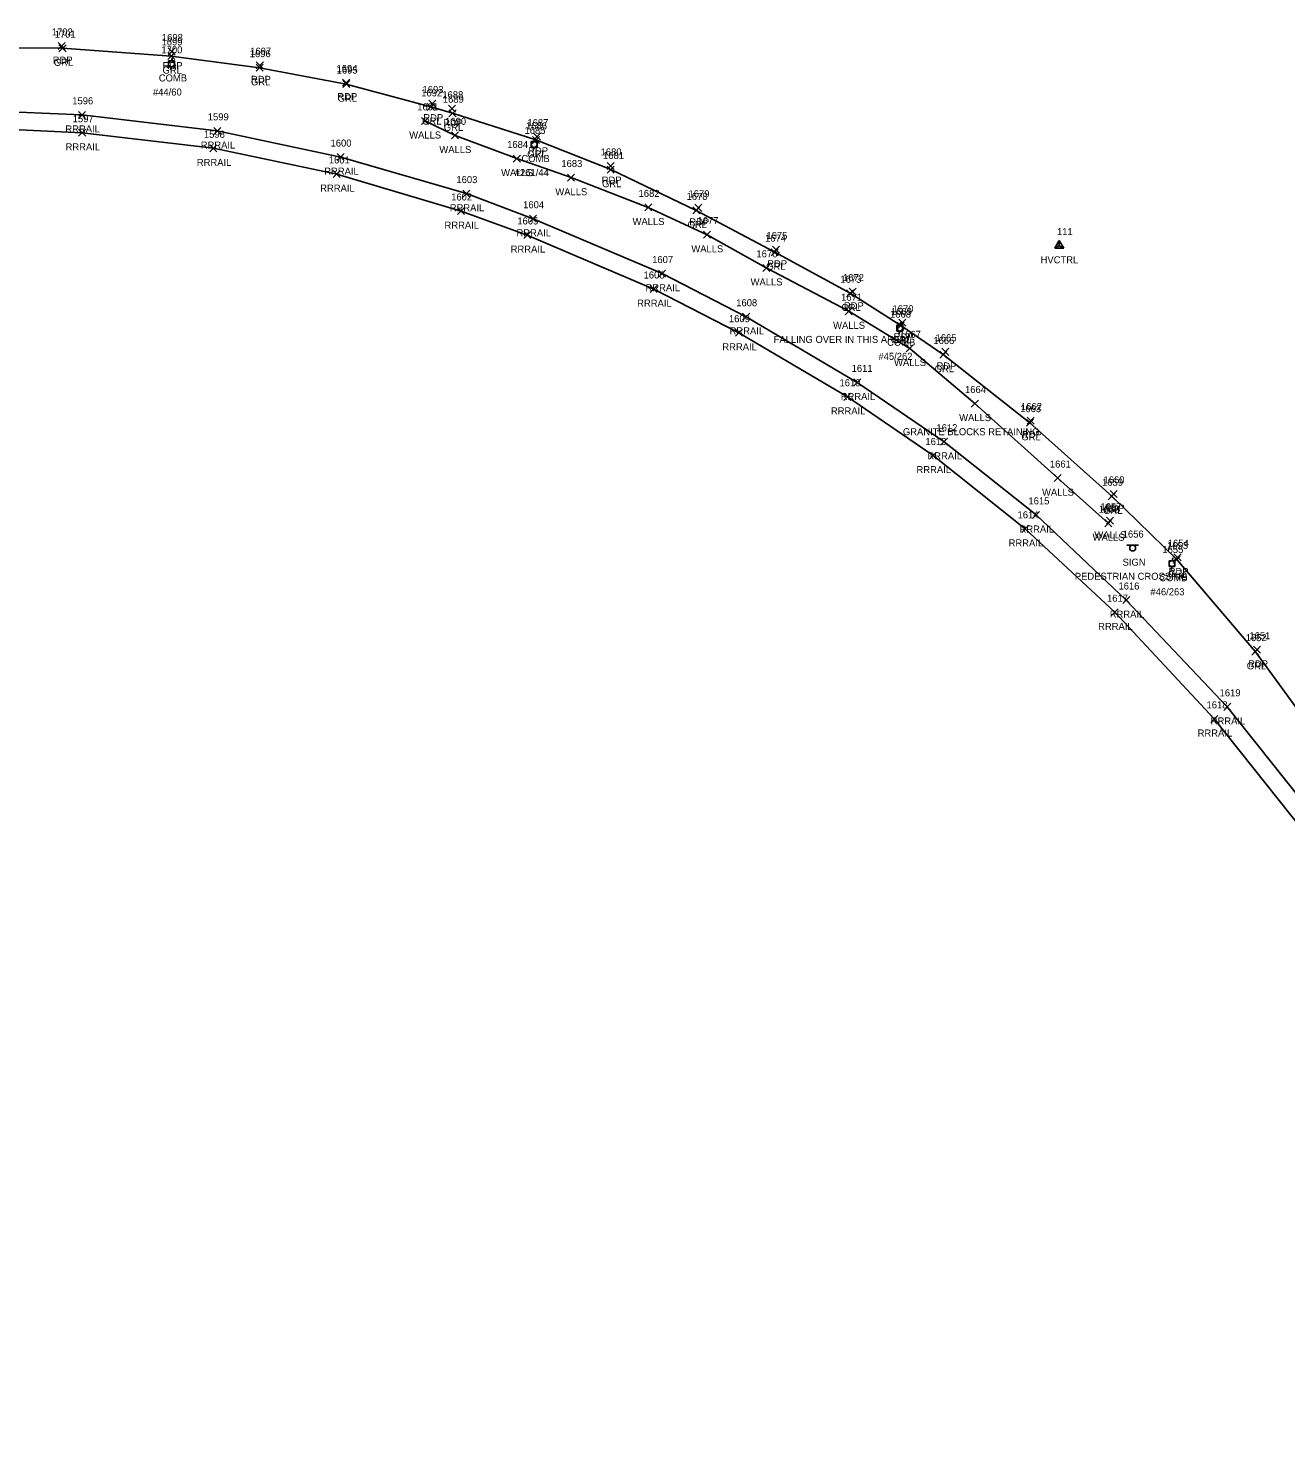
# Model space of a CAD drawing. Extents: x 1635588 to 1637550, y 621583 to 623638.
# Drawn here: x 1635936.7 to 1636293.9, y 623212.1 to 623614.3 of the extents above; entities that cross this region are included whole.
import ezdxf

# ---------------------------------------------------------------- set-up
doc = ezdxf.new("R2010")
doc.units = 0
for name, color, linetype in [('C_A', 7, 'Continuous'), ('C_I', 7, 'Continuous'), ('CPSM', 7, 'Continuous'), ('L_A', 7, 'Continuous'), ('L_C', 7, 'Continuous'), ('L_I', 7, 'Continuous'), ('L_TIC', 7, 'Continuous'), ('LWS', 7, 'Continuous'), ('P_A', 7, 'Continuous'), ('P_I', 7, 'Continuous'), ('P_TIC', 7, 'Continuous'), ('R_A', 7, 'Continuous'), ('R_I', 7, 'Continuous'), ('R_TIC', 7, 'Continuous'), ('RGR', 7, 'Continuous'), ('RR', 7, 'Continuous'), ('S_A', 7, 'Continuous'), ('S_C', 7, 'Continuous'), ('S_I', 7, 'Continuous'), ('SSGN', 7, 'Continuous'), ('U_A', 7, 'Continuous'), ('U_C', 7, 'Continuous'), ('U_I', 7, 'Continuous'), ('UP', 7, 'Continuous')]:
    doc.layers.add(name, color=color, linetype=linetype)

msp = doc.modelspace()

# ---------------------------------------------------------------- linework, layer by layer
at = {"layer": 'CPSM'}
for p, q in [((1636228.33, 623551.79), (1636229.58, 623553.95)), ((1636230.83, 623551.79), (1636229.58, 623553.95)), ((1636229.58, 623552.51), (1636229.58, 623553.95)), ((1636228.33, 623551.79), (1636229.58, 623552.51)), ((1636228.33, 623551.79), (1636230.83, 623551.79)), ((1636229.58, 623552.51), (1636229.58, 623552.51)), ((1636229.58, 623552.51), (1636230.83, 623551.79))]:
    msp.add_line(p, q, dxfattribs=at)
at = {"layer": 'L_TIC'}
for points in [[(1636048.39, 623586.97), (1636050.39, 623588.97)], [(1636050.39, 623586.97), (1636048.39, 623588.97)], [(1636056.96, 623582.85), (1636058.96, 623584.85)], [(1636058.96, 623582.85), (1636056.96, 623584.85)], [(1636074.5, 623576.28), (1636076.5, 623578.28)], [(1636076.5, 623576.28), (1636074.5, 623578.28)], [(1636089.89, 623570.85), (1636091.89, 623572.85)], [(1636091.89, 623570.85), (1636089.89, 623572.85)], [(1636111.82, 623562.38), (1636113.82, 623564.38)], [(1636113.82, 623562.38), (1636111.82, 623564.38)], [(1636128.53, 623554.64), (1636130.53, 623556.64)], [(1636130.53, 623554.64), (1636128.53, 623556.64)], [(1636145.36, 623545.21), (1636147.36, 623547.21)], [(1636147.36, 623545.21), (1636145.36, 623547.21)], [(1636168.79, 623532.89), (1636170.79, 623534.89)], [(1636170.79, 623532.89), (1636168.79, 623534.89)], [(1636186.1, 623522.33), (1636188.1, 623524.33)], [(1636188.1, 623522.33), (1636186.1, 623524.33)], [(1636204.59, 623506.66), (1636206.59, 623508.66)], [(1636206.59, 623506.66), (1636204.59, 623508.66)], [(1636228.13, 623485.47), (1636230.13, 623487.47)], [(1636230.13, 623485.47), (1636228.13, 623487.47)], [(1636242.5, 623472.67), (1636244.5, 623474.67)], [(1636244.5, 623472.67), (1636242.5, 623474.67)], [(1636242.99, 623473.35), (1636244.99, 623475.35)], [(1636244.99, 623473.35), (1636242.99, 623475.35)]]:
    msp.add_lwpolyline(points, dxfattribs=at)
at = {"layer": 'LWS'}
msp.add_lwpolyline([(1636243.99, 623474.35), (1636243.5, 623473.67), (1636229.13, 623486.47), (1636205.59, 623507.66), (1636187.1, 623523.33), (1636169.79, 623533.89), (1636146.36, 623546.21), (1636129.53, 623555.64), (1636112.82, 623563.38), (1636090.89, 623571.85), (1636075.5, 623577.28), (1636057.96, 623583.85), (1636049.39, 623587.97)], dxfattribs=at)
at = {"layer": 'P_TIC'}
for points in [[(1635945.19, 623608.25), (1635947.19, 623610.25)], [(1635947.19, 623608.25), (1635945.19, 623610.25)], [(1635976.43, 623606.69), (1635978.43, 623608.69)], [(1635978.43, 623606.69), (1635976.43, 623608.69)], [(1636001.51, 623602.78), (1636003.51, 623604.78)], [(1636003.51, 623602.78), (1636001.51, 623604.78)], [(1636026.03, 623597.88), (1636028.03, 623599.88)], [(1636028.03, 623597.88), (1636026.03, 623599.88)], [(1636050.46, 623591.89), (1636052.46, 623593.89)], [(1636052.46, 623591.89), (1636050.46, 623593.89)], [(1636056.08, 623590.41), (1636058.08, 623592.41)], [(1636058.08, 623590.41), (1636056.08, 623592.41)], [(1636080.24, 623582.48), (1636082.24, 623584.48)], [(1636082.24, 623582.48), (1636080.24, 623584.48)], [(1636101.12, 623574.17), (1636103.12, 623576.17)], [(1636103.12, 623574.17), (1636101.12, 623576.17)], [(1636126.02, 623562.27), (1636128.02, 623564.27)], [(1636128.02, 623562.27), (1636126.02, 623564.27)], [(1636148.13, 623550.4), (1636150.13, 623552.4)], [(1636150.13, 623550.4), (1636148.13, 623552.4)], [(1636169.89, 623538.45), (1636171.89, 623540.45)], [(1636171.89, 623538.45), (1636169.89, 623540.45)], [(1636184.03, 623529.61), (1636186.03, 623531.61)], [(1636186.03, 623529.61), (1636184.03, 623531.61)], [(1636196.22, 623521.36), (1636198.22, 623523.36)], [(1636198.22, 623521.36), (1636196.22, 623523.36)], [(1636220.48, 623501.83), (1636222.48, 623503.83)], [(1636222.48, 623501.83), (1636220.48, 623503.83)], [(1636244.02, 623480.98), (1636246.02, 623482.98)], [(1636246.02, 623480.98), (1636244.02, 623482.98)], [(1636262.15, 623462.97), (1636264.15, 623464.97)], [(1636264.15, 623462.97), (1636262.15, 623464.97)], [(1636284.73, 623436.69), (1636286.73, 623438.69)], [(1636286.73, 623436.69), (1636284.73, 623438.69)]]:
    msp.add_lwpolyline(points, dxfattribs=at)
at = {"layer": 'R_TIC'}
for points in [[(1635945.46, 623607.63), (1635947.46, 623609.63)], [(1635947.46, 623607.63), (1635945.46, 623609.63)], [(1635976.33, 623605.41), (1635978.33, 623607.41)], [(1635978.33, 623605.41), (1635976.33, 623607.41)], [(1636001.44, 623602.08), (1636003.44, 623604.08)], [(1636003.44, 623602.08), (1636001.44, 623604.08)], [(1636026.07, 623597.42), (1636028.07, 623599.42)], [(1636028.07, 623597.42), (1636026.07, 623599.42)], [(1635950.97, 623588.69), (1635952.97, 623590.69)], [(1635952.97, 623588.69), (1635950.97, 623590.69)], [(1636050.08, 623590.93), (1636052.08, 623592.93)], [(1636052.08, 623590.93), (1636050.08, 623592.93)], [(1636056.23, 623589.14), (1636058.23, 623591.14)], [(1636058.23, 623589.14), (1636056.23, 623591.14)], [(1635951.04, 623583.59), (1635953.04, 623585.59)], [(1635953.04, 623583.59), (1635951.04, 623585.59)], [(1635989.42, 623584.12), (1635991.42, 623586.12)], [(1635991.42, 623584.12), (1635989.42, 623586.12)], [(1635988.32, 623579.18), (1635990.32, 623581.18)], [(1635990.32, 623579.18), (1635988.32, 623581.18)], [(1636079.92, 623581.58), (1636081.92, 623583.58)], [(1636081.92, 623581.58), (1636079.92, 623583.58)], [(1636024.5, 623576.68), (1636026.5, 623578.68)], [(1636026.5, 623576.68), (1636024.5, 623578.68)], [(1636023.35, 623571.88), (1636025.35, 623573.88)], [(1636025.35, 623571.88), (1636023.35, 623573.88)], [(1636101.16, 623573.13), (1636103.16, 623575.13)], [(1636103.16, 623573.13), (1636101.16, 623575.13)], [(1636060.16, 623566.3), (1636062.16, 623568.3)], [(1636062.16, 623566.3), (1636060.16, 623568.3)], [(1636058.67, 623561.36), (1636060.67, 623563.36)], [(1636060.67, 623561.36), (1636058.67, 623563.36)], [(1636079.11, 623559.16), (1636081.11, 623561.16)], [(1636081.11, 623559.16), (1636079.11, 623561.16)], [(1636125.46, 623561.53), (1636127.46, 623563.53)], [(1636127.46, 623561.53), (1636125.46, 623563.53)], [(1636077.46, 623554.55), (1636079.46, 623556.55)], [(1636079.46, 623554.55), (1636077.46, 623556.55)], [(1636147.75, 623549.67), (1636149.75, 623551.67)], [(1636149.75, 623549.67), (1636147.75, 623551.67)], [(1636115.76, 623543.58), (1636117.76, 623545.58)], [(1636117.76, 623543.58), (1636115.76, 623545.58)], [(1636113.37, 623539.19), (1636115.37, 623541.19)], [(1636115.37, 623539.19), (1636113.37, 623541.19)], [(1636169.14, 623537.98), (1636171.14, 623539.98)], [(1636171.14, 623537.98), (1636169.14, 623539.98)], [(1636139.64, 623531.31), (1636141.64, 623533.31)], [(1636141.64, 623531.31), (1636139.64, 623533.31)], [(1636183.56, 623528.81), (1636185.56, 623530.81)], [(1636185.56, 623528.81), (1636183.56, 623530.81)], [(1636137.58, 623526.78), (1636139.58, 623528.78)], [(1636139.58, 623526.78), (1636137.58, 623528.78)], [(1636195.64, 623520.56), (1636197.64, 623522.56)], [(1636197.64, 623520.56), (1636195.64, 623522.56)], [(1636171.21, 623512.66), (1636173.21, 623514.66)], [(1636173.21, 623512.66), (1636171.21, 623514.66)], [(1636168.41, 623508.57), (1636170.41, 623510.57)], [(1636170.41, 623508.57), (1636168.41, 623510.57)], [(1636220.25, 623501.22), (1636222.25, 623503.22)], [(1636222.25, 623501.22), (1636220.25, 623503.22)], [(1636195.85, 623495.79), (1636197.85, 623497.79)], [(1636197.85, 623495.79), (1636195.85, 623497.79)], [(1636192.73, 623491.88), (1636194.73, 623493.88)], [(1636194.73, 623491.88), (1636192.73, 623493.88)], [(1636243.49, 623480.3), (1636245.49, 623482.3)], [(1636245.49, 623480.3), (1636243.49, 623482.3)], [(1636222, 623475.01), (1636224, 623477.01)], [(1636224, 623475.01), (1636222, 623477.01)], [(1636218.9, 623471.06), (1636220.9, 623473.06)], [(1636220.9, 623471.06), (1636218.9, 623473.06)], [(1636261.93, 623462.31), (1636263.93, 623464.31)], [(1636263.93, 623462.31), (1636261.93, 623464.31)], [(1636247.62, 623450.82), (1636249.62, 623452.82)], [(1636249.62, 623450.82), (1636247.62, 623452.82)], [(1636244.31, 623447.34), (1636246.31, 623449.34)], [(1636246.31, 623447.34), (1636244.31, 623449.34)], [(1636284.27, 623436.15), (1636286.27, 623438.15)], [(1636286.27, 623436.15), (1636284.27, 623438.15)], [(1636276.3, 623420.48), (1636278.3, 623422.48)], [(1636278.3, 623420.48), (1636276.3, 623422.48)], [(1636272.58, 623417.05), (1636274.58, 623419.05)], [(1636274.58, 623417.05), (1636272.58, 623419.05)]]:
    msp.add_lwpolyline(points, dxfattribs=at)
at = {"layer": 'RGR'}
msp.add_lwpolyline([(1636305.19, 623409.8), (1636285.27, 623437.15), (1636262.93, 623463.31), (1636244.49, 623481.3), (1636221.25, 623502.22), (1636196.64, 623521.56), (1636184.56, 623529.81), (1636170.14, 623538.98), (1636148.75, 623550.67), (1636126.46, 623562.53), (1636102.16, 623574.13), (1636080.92, 623582.58), (1636057.23, 623590.14), (1636051.08, 623591.93), (1636027.07, 623598.42), (1636002.44, 623603.08), (1635977.33, 623606.41), (1635946.46, 623608.63), (1635912.43, 623608.87), (1635865.23, 623607.69), (1635827.72, 623606.97)], dxfattribs=at)
at = {"layer": 'RR'}
for points in [[(1635804.38, 623587.78), (1635886, 623591.18), (1635924.86, 623590.87), (1635951.97, 623589.69), (1635990.42, 623585.12), (1636025.5, 623577.68), (1636061.16, 623567.3), (1636080.11, 623560.16), (1636116.76, 623544.58), (1636140.64, 623532.31), (1636172.21, 623513.66), (1636196.85, 623496.79), (1636223, 623476.01), (1636248.62, 623451.82), (1636277.3, 623421.48), (1636310.55, 623379.63), (1636333.74, 623345.07), (1636353.23, 623312.06), (1636372.67, 623275.5), (1636403.41, 623214.43)], [(1635804.54, 623582.78), (1635886.42, 623586.09), (1635924.26, 623585.89), (1635952.04, 623584.59), (1635989.32, 623580.18), (1636024.35, 623572.88), (1636059.67, 623562.36), (1636078.46, 623555.55), (1636114.37, 623540.19), (1636138.58, 623527.78), (1636169.41, 623509.57), (1636193.73, 623492.88), (1636219.9, 623472.06), (1636245.31, 623448.34), (1636273.58, 623418.05), (1636306.45, 623376.76), (1636329.74, 623342.31), (1636348.93, 623309.65), (1636368.15, 623273.24), (1636399.35, 623212.11)]]:
    msp.add_lwpolyline(points, dxfattribs=at)
at = {"layer": 'SSGN'}
for p, q in [((1636248.76, 623467.43), (1636252.09, 623467.43)), ((1636250.41, 623466.6), (1636250.41, 623466.6))]:
    msp.add_line(p, q, dxfattribs=at)
msp.add_circle((1636250.41, 623466.6), 0.833, dxfattribs=at)
at = {"layer": 'UP'}
for p, q in [((1635977.67, 623605.85), (1635977.42, 623605.01)), ((1635976.59, 623603.35), (1635976.59, 623605.01)), ((1635976.59, 623605.01), (1635978.26, 623605.01)), ((1635978.26, 623603.35), (1635976.59, 623603.35)), ((1635977.17, 623602.51), (1635977.42, 623603.35)), ((1635977.42, 623604.18), (1635977.42, 623604.18)), ((1635978.26, 623605.01), (1635978.26, 623603.35)), ((1636079.59, 623580.45), (1636079.59, 623582.12)), ((1636079.59, 623582.12), (1636081.26, 623582.12)), ((1636080.67, 623582.95), (1636080.42, 623582.12)), ((1636080.42, 623581.28), (1636080.42, 623581.28)), ((1636081.26, 623582.12), (1636081.26, 623580.45)), ((1636081.26, 623580.45), (1636079.59, 623580.45)), ((1636080.17, 623579.62), (1636080.42, 623580.45)), ((1636183.45, 623528.25), (1636183.45, 623529.92)), ((1636183.45, 623529.92), (1636185.12, 623529.92)), ((1636184.54, 623530.75), (1636184.29, 623529.92)), ((1636184.29, 623529.08), (1636184.29, 623529.08)), ((1636185.12, 623529.92), (1636185.12, 623528.25)), ((1636185.12, 623528.25), (1636183.45, 623528.25)), ((1636184.04, 623527.42), (1636184.29, 623528.25)), ((1636260.76, 623461.34), (1636260.76, 623463.01)), ((1636260.76, 623463.01), (1636262.43, 623463.01)), ((1636262.43, 623461.34), (1636260.76, 623461.34)), ((1636261.35, 623460.51), (1636261.6, 623461.34)), ((1636261.85, 623463.84), (1636261.6, 623463.01)), ((1636261.6, 623462.18), (1636261.6, 623462.18)), ((1636262.43, 623463.01), (1636262.43, 623461.34))]:
    msp.add_line(p, q, dxfattribs=at)
for centre in [(1635977.42, 623604.18), (1636080.42, 623581.28), (1636184.29, 623529.08), (1636261.6, 623462.18)]:
    msp.add_circle(centre, 0.833, dxfattribs=at)

# ---------------------------------------------------------------- texts
at = {"layer": 'C_A'}
msp.add_text('HVCTRL', height=2, dxfattribs=at).set_placement((1636224.27, 623547.51))
at = {"layer": 'C_I'}
msp.add_text('111', height=2, dxfattribs=at).set_placement((1636228.92, 623555.51))
at = {"layer": 'L_A'}
for p in [(1636044.93, 623582.97), (1636053.5, 623578.85), (1636071.04, 623572.28), (1636086.44, 623566.85), (1636108.37, 623558.38), (1636125.07, 623550.64), (1636141.9, 623541.21), (1636165.33, 623528.89), (1636182.65, 623518.33), (1636201.14, 623502.66), (1636224.68, 623481.47), (1636239.04, 623468.67), (1636239.54, 623469.35)]:
    msp.add_text('WALLS', height=2, dxfattribs=at).set_placement(p)
at = {"layer": 'L_C'}
for s, p in [('FALLING OVER IN THIS AREA', (1636148.43, 623524.89)), ('GRANITE BLOCKS RETAINING', (1636185.16, 623498.66))]:
    msp.add_text(s, height=2, dxfattribs=at).set_placement(p)
at = {"layer": 'L_I'}
for s, p in [('1691', (1636047.22, 623590.97)), ('1690', (1636055.13, 623586.85)), ('1684', (1636072.76, 623580.28)), ('1683', (1636088.15, 623574.85)), ('1682', (1636110.08, 623566.38)), ('1677', (1636126.79, 623558.64)), ('1676', (1636143.56, 623549.21)), ('1671', (1636167.61, 623536.89)), ('1667', (1636184.32, 623526.33)), ('1664', (1636202.8, 623510.66)), ('1661', (1636226.91, 623489.47)), ('1658', (1636240.76, 623476.67)), ('1657', (1636241.25, 623477.35))]:
    msp.add_text(s, height=2, dxfattribs=at).set_placement(p)
at = {"layer": 'P_A'}
for p in [(1635943.68, 623604.25), (1635974.92, 623602.69), (1635999.99, 623598.78), (1636024.52, 623593.88), (1636048.95, 623587.89), (1636054.56, 623586.41), (1636078.72, 623578.48), (1636099.61, 623570.17), (1636124.5, 623558.27), (1636146.62, 623546.4), (1636168.38, 623534.45), (1636182.52, 623525.61), (1636194.71, 623517.36), (1636218.97, 623497.83), (1636242.51, 623476.98), (1636260.64, 623458.97), (1636283.22, 623432.69)]:
    msp.add_text('RDP', height=2, dxfattribs=at).set_placement(p)
at = {"layer": 'P_I'}
for s, p in [('1702', (1635943.42, 623612.25)), ('1698', (1635974.69, 623610.69)), ('1697', (1635999.77, 623606.78)), ('1694', (1636024.29, 623601.88)), ('1693', (1636048.72, 623595.89)), ('1688', (1636054.34, 623594.41)), ('1687', (1636078.5, 623586.48)), ('1680', (1636099.29, 623578.17)), ('1679', (1636124.27, 623566.27)), ('1675', (1636146.39, 623554.4)), ('1672', (1636168.15, 623542.45)), ('1670', (1636182.21, 623533.61)), ('1665', (1636194.44, 623525.36)), ('1662', (1636218.69, 623505.83)), ('1660', (1636242.15, 623484.98)), ('1654', (1636260.41, 623466.97)), ('1651', (1636283.56, 623440.69))]:
    msp.add_text(s, height=2, dxfattribs=at).set_placement(p)
at = {"layer": 'R_A'}
for s, p in [('GRL', (1635944, 623603.63)), ('GRL', (1635974.87, 623601.41)), ('GRL', (1635999.98, 623598.08)), ('GRL', (1636024.61, 623593.42)), ('RRRAIL', (1635947.27, 623584.69)), ('GRL', (1636048.62, 623586.93)), ('GRL', (1636054.77, 623585.14)), ('RRRAIL', (1635947.33, 623579.59)), ('RRRAIL', (1635985.72, 623580.12)), ('RRRAIL', (1635984.61, 623575.18)), ('GRL', (1636078.46, 623577.58)), ('RRRAIL', (1636020.79, 623572.68)), ('RRRAIL', (1636019.65, 623567.88)), ('GRL', (1636099.7, 623569.13)), ('RRRAIL', (1636056.45, 623562.3)), ('RRRAIL', (1636054.96, 623557.36)), ('RRRAIL', (1636075.4, 623555.16)), ('GRL', (1636124, 623557.53)), ('RRRAIL', (1636073.75, 623550.55)), ('GRL', (1636146.3, 623545.67)), ('RRRAIL', (1636112.05, 623539.58)), ('RRRAIL', (1636109.67, 623535.19)), ('GRL', (1636167.68, 623533.98)), ('RRRAIL', (1636135.93, 623527.31)), ('GRL', (1636182.1, 623524.81)), ('RRRAIL', (1636133.87, 623522.78)), ('GRL', (1636194.18, 623516.56)), ('RRRAIL', (1636167.5, 623508.66)), ('RRRAIL', (1636164.71, 623504.57)), ('GRL', (1636218.8, 623497.22)), ('RRRAIL', (1636192.14, 623491.79)), ('RRRAIL', (1636189.02, 623487.88)), ('GRL', (1636242.03, 623476.3)), ('RRRAIL', (1636218.29, 623471.01)), ('RRRAIL', (1636215.19, 623467.06)), ('GRL', (1636260.48, 623458.31)), ('RRRAIL', (1636243.91, 623446.82)), ('RRRAIL', (1636240.6, 623443.34)), ('GRL', (1636282.82, 623432.15)), ('RRRAIL', (1636272.59, 623416.48)), ('RRRAIL', (1636268.87, 623413.05))]:
    msp.add_text(s, height=2, dxfattribs=at).set_placement(p)
at = {"layer": 'R_I'}
for s, p in [('1701', (1635944.25, 623611.63)), ('1699', (1635974.58, 623609.41)), ('1696', (1635999.64, 623606.08)), ('1695', (1636024.33, 623601.42)), ('1596', (1635949.23, 623592.69)), ('1692', (1636048.34, 623594.93)), ('1689', (1636054.48, 623593.14)), ('1597', (1635949.35, 623587.59)), ('1599', (1635987.72, 623588.12)), ('1598', (1635986.63, 623583.18)), ('1686', (1636078.12, 623585.58)), ('1600', (1636022.59, 623580.68)), ('1601', (1636022.1, 623575.88)), ('1681', (1636099.99, 623577.13)), ('1603', (1636058.34, 623570.3)), ('1602', (1636056.85, 623565.36)), ('1604', (1636077.29, 623563.16)), ('1678', (1636123.72, 623565.53)), ('1605', (1636075.64, 623558.55)), ('1674', (1636146.01, 623553.67)), ('1607', (1636113.94, 623547.58)), ('1606', (1636111.5, 623543.19)), ('1673', (1636167.4, 623541.98)), ('1608', (1636137.82, 623535.31)), ('1669', (1636181.76, 623532.81)), ('1609', (1636135.75, 623530.78)), ('1666', (1636193.8, 623524.56)), ('1611', (1636170.6, 623516.66)), ('1610', (1636167.15, 623512.57)), ('1663', (1636218.46, 623505.22)), ('1612', (1636194.68, 623499.79)), ('1613', (1636191.55, 623495.88)), ('1659', (1636241.74, 623484.3)), ('1615', (1636220.82, 623479.01)), ('1614', (1636217.73, 623475.06)), ('1653', (1636260.19, 623466.31)), ('1616', (1636246.39, 623454.82)), ('1617', (1636243.13, 623451.34)), ('1652', (1636282.53, 623440.15)), ('1619', (1636275.11, 623424.48)), ('1618', (1636271.4, 623421.05))]:
    msp.add_text(s, height=2, dxfattribs=at).set_placement(p)
at = {"layer": 'S_A'}
msp.add_text('SIGN', height=2, dxfattribs=at).set_placement((1636247.55, 623461.58))
at = {"layer": 'S_C'}
msp.add_text('PEDESTRIAN CROSSING', height=2, dxfattribs=at).set_placement((1636233.99, 623457.58))
at = {"layer": 'S_I'}
msp.add_text('1656', height=2, dxfattribs=at).set_placement((1636247.59, 623469.58))
at = {"layer": 'U_A'}
for p in [(1635973.81, 623599.18), (1636076.81, 623576.28), (1636180.67, 623524.08), (1636257.98, 623457.18)]:
    msp.add_text('COMB', height=2, dxfattribs=at).set_placement(p)
at = {"layer": 'U_C'}
for s, p in [('#44/60', (1635972.15, 623595.18)), ('#261/44', (1636074.91, 623572.28)), ('#45/262', (1636178.21, 623520.08)), ('#46/263', (1636255.47, 623453.18))]:
    msp.add_text(s, height=2, dxfattribs=at).set_placement(p)
at = {"layer": 'U_I'}
for s, p in [('1700', (1635974.56, 623607.18)), ('1685', (1636077.68, 623584.28)), ('1668', (1636181.5, 623532.08)), ('1655', (1636258.86, 623465.18))]:
    msp.add_text(s, height=2, dxfattribs=at).set_placement(p)

doc.saveas('drawing.dxf')
